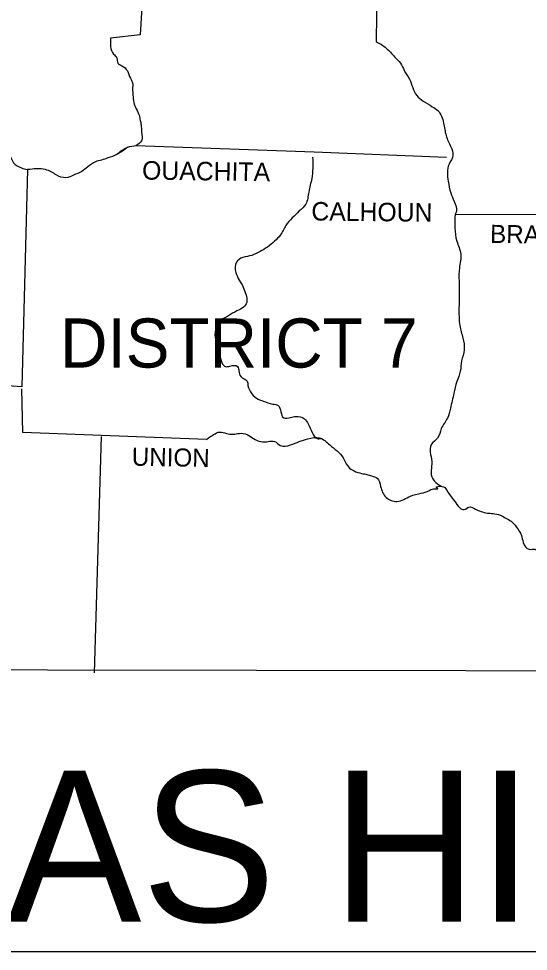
# Model space of a CAD drawing. Extents: x -17742 to 32032, y -17264 to 5867.
# Drawn here: x 2462 to 3114, y 2539 to 3730 of the extents above; entities that cross this region are included whole.
import ezdxf

# ---------------------------------------------------------------- set-up
doc = ezdxf.new("R2010")
doc.units = 0
for name, color, linetype in [('1', 7, 'Continuous'), ('2', 7, 'Continuous'), ('3', 7, 'Continuous')]:
    doc.layers.add(name, color=color, linetype=linetype)

msp = doc.modelspace()

# ---------------------------------------------------------------- linework, layer by layer
at = {"layer": '1'}
msp.add_line((1374.2, 2539.3), (4887.3, 2539.3), dxfattribs=at)
for points in [[(2626.1, 3851.4), (2617.8, 3709.9), (2579.8, 3705.5)], [(3001.4, 3774.9), (2920, 3769.9), (2919.4, 3701.1)], [(2612.3, 3568.5), (2840.2, 3560.2), (3009.1, 3553.6)], [(2473.6, 3537.6), (2466.5, 3260.3), (2392.2, 3265.2), (2391.6, 3244.9), (2292.6, 3250.9)], [(3020.1, 3480.4), (3268.9, 3481)], [(2702.6, 3193.1), (2467.6, 3201.9), (2466.5, 3257.5)], [(2567.7, 3197), (2558.9, 2894.8)], [(1964.6, 2899.5), (3835.2, 2896.5)]]:
    msp.add_lwpolyline(points, dxfattribs=at)
for points in [[(2201.8, 3910.8), (2210.6, 3905.3), (2221, 3900.3), (2226.5, 3892.1), (2228.7, 3879.4), (2232.6, 3865.7), (2233.7, 3851.4), (2230.4, 3843.6), (2234.8, 3826), (2236.4, 3813.9), (2238.1, 3799.6), (2242.5, 3780.4), (2249.6, 3767.1), (2256.2, 3751.2), (2267.2, 3734.1), (2276.6, 3715.4), (2281, 3705.5), (2289.3, 3685.1), (2299.7, 3671.4), (2316.2, 3650.5), (2331.1, 3629), (2339.3, 3613), (2352, 3595.4), (2366.3, 3586.6), (2384.5, 3577.3), (2396, 3571.8), (2409.2, 3562.4), (2426.3, 3561.3), (2439, 3561.3), (2450.5, 3556.4), (2456, 3546.5), (2465.9, 3539.9), (2473.6, 3537.6)], [(2579.8, 3705.5), (2579.8, 3695), (2583.7, 3685.1), (2587.6, 3680.7), (2589.2, 3673.6), (2594.2, 3670.3), (2601.3, 3663.7), (2605.2, 3654.3), (2607.9, 3648.3), (2607.9, 3640.6), (2608.5, 3632.9), (2609.6, 3623.5), (2616.2, 3607), (2617.8, 3600.4), (2618.9, 3594.9), (2619.5, 3585.5), (2619.5, 3574.5), (2612.3, 3568.5)], [(2919.4, 3701.1), (2932.1, 3692.8), (2942.5, 3681.8), (2950.2, 3673.6), (2955.2, 3664.2), (2961.8, 3653.2), (2971.1, 3632.3), (2979.4, 3625.2), (2991, 3618), (2998.1, 3613), (3005.3, 3597.1), (3008.6, 3581.1), (3014.6, 3566.8), (3017.4, 3555.8), (3012.4, 3544.8), (3011.3, 3522.8), (3014.6, 3507.9), (3019, 3496.9), (3021.8, 3484.3), (3020.1, 3480.4)], [(2601.9, 3566.3), (2587.6, 3556.9), (2576.5, 3552.5), (2568.3, 3549.8), (2560.6, 3547.6), (2550.7, 3541), (2543, 3535.4), (2532.5, 3530.5), (2522.6, 3527.2), (2510.5, 3531), (2503.9, 3534.9), (2496.7, 3537.6), (2473.6, 3537.6)], [(2587.6, 3556.9), (2601.9, 3566.3), (2612.3, 3568.5)], [(2838, 3553.6), (2836.9, 3526.1), (2833, 3509), (2829.2, 3493.6), (2820.9, 3484.8), (2812.1, 3476), (2803.8, 3466.1), (2796.7, 3454), (2789.5, 3446.3), (2780.2, 3438.6), (2770.8, 3433.1), (2760.4, 3428.1), (2748.8, 3425.4), (2740.6, 3419.3), (2740, 3406.1), (2749.4, 3387.4), (2752.7, 3378.6), (2753.8, 3368.1), (2749.9, 3362.1), (2741.1, 3357.1), (2730.6, 3351.1), (2721.3, 3345.6), (2714.7, 3336.2), (2713.6, 3323.6), (2718, 3308.7), (2719.6, 3299.9), (2726.8, 3286.1), (2732.3, 3286.7), (2742.2, 3286.1), (2743.3, 3283.4), (2743.9, 3280.6), (2746.1, 3273.5), (2754.3, 3267.4), (2755.4, 3261.9), (2760.4, 3251.5), (2768.6, 3244.3), (2774.7, 3242.1), (2787.3, 3238.3), (2793.9, 3236.6), (2801.1, 3220.6), (2809.9, 3221.2), (2816.5, 3222.3), (2827.5, 3219.5), (2832.5, 3212.9), (2837.4, 3201.9), (2844, 3194.2), (2848.4, 3194.2)], [(3020.1, 3480.4), (3022.3, 3446.3), (3027.3, 3429.8), (3025.6, 3412.2), (3025.1, 3395.1), (3025.1, 3379.7), (3025.1, 3364.8), (3025.1, 3349.4), (3026.2, 3338.4), (3030, 3322.5), (3031.7, 3307.6), (3028.4, 3293.3), (3026.7, 3280.1), (3022.3, 3266.9), (3018.5, 3252), (3014.1, 3232.8), (3010.2, 3220.1), (3002.5, 3206.9), (2997.6, 3194.8), (2989.9, 3187.1), (2988.8, 3173.9), (2990.4, 3161.8), (2989.3, 3150.7), (2993.2, 3140.3), (3003.1, 3133.1)], [(2702.6, 3193.1), (2711.4, 3199.2), (2719.6, 3202.5), (2727.9, 3200.8), (2736.7, 3199.7), (2744.4, 3200.8), (2754.3, 3199.2), (2762.6, 3194.2), (2771.9, 3190.4), (2781.3, 3190.4), (2789.5, 3190.4), (2796.7, 3185.4), (2809.9, 3186), (2820.9, 3190.4), (2831.9, 3193.7), (2846.8, 3195.3), (2860, 3186), (2869.3, 3178.3), (2877, 3169.5), (2882.5, 3159.6), (2888.6, 3154.1), (2898.5, 3150.2), (2906.2, 3148.5), (2915.6, 3145.8), (2920.5, 3143.6), (2924.9, 3133.1), (2932.1, 3118.8), (2945.8, 3113.9), (2962.9, 3120.5), (2976.7, 3124.3), (2986.6, 3127.6), (2992.6, 3129.8), (2998.1, 3130.4), (2996.5, 3131.5), (3003.1, 3133.1), (3009.1, 3128.7), (3013, 3122.7), (3019.6, 3113.9), (3025.6, 3106.2), (3031.7, 3103.4), (3037.7, 3106.7), (3046, 3104), (3053.2, 3101.2), (3061.4, 3099), (3068.6, 3098.5), (3077.9, 3096.3), (3085.1, 3092.4), (3091.7, 3088.6), (3098.3, 3081.4), (3104.9, 3070.4), (3107.1, 3061.6), (3114.8, 3052.8), (3121.9, 3052.8), (3132.4, 3038.5), (3136.3, 3033), (3144.5, 3023.1), (3150.6, 3023.1), (3162.1, 3020.9)]]:
    msp.add_spline(points, degree=3, dxfattribs=at)

# ---------------------------------------------------------------- texts
at = {"layer": '2'}
for s, height, rotation, p in [('OUACHITA', 23.67, 359.2043, (2620, 3525)), ('CALHOUN', 23.67, 359.3634, (2836.3, 3472.7)), ('BRADLEY', 23.11, 359.1449, (3064.7, 3444.1)), ('UNION', 23.11, 358.9584, (2606.8, 3159.6))]:
    msp.add_text(s, height=height, rotation=rotation, dxfattribs=at).set_placement(p)
msp.add_text('ARKANSAS HIGHWAY DISTRICT 3', height=192.623, dxfattribs=at).set_placement((1388.2, 2577.3))
at = {"layer": '3'}
msp.add_text('DISTRICT 7', height=62.74, dxfattribs=at).set_placement((2515.3, 3284.8))

doc.saveas('drawing.dxf')
